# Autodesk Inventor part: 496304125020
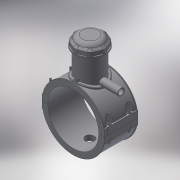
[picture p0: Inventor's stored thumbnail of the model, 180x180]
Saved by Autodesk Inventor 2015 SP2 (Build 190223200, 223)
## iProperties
Created: 2017-07
Part Number: 496304125020
Material: Generic
Description: PLASSON TAPPING SADDLE 125x20
Document SubType Name: Modeling
Designer: KIM
Mass: 805.718 g
Surface Area: 1766.05 cm^2
Volume: 805.718 cm^3
Density: 1 g/cm^3
Appearance: Default
Author: KIM
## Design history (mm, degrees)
derived "496304.ipt"
feature "Solid1::496304.ipt"
feature "Solid2::496304.ipt"
feature "Solid4::496304.ipt"
feature "Solid5::496304.ipt"
tag "TaggingFeature1"
body "Solid1"
body "Solid2"
other parameters: "d0" = 125, "d2" = 162, "d3" = 31.25, "d4" = 118, "d5" = 0, "d6" = 0.1, "d8" = 0, "d19" = 6, "d20" = 6, "d21" = 70.8, "d23" = 0, "d24" = 35.4, "d26" = 0, "d29" = 3, "d30" = 41.66667, "d31" = 6, "d32" = 0, "d33" = 0, "d34" = 0.6, "d40" = 78, "d41" = 62.5, "d43" = 0, "d45" = 0, "d47" = 145.8, "d70" = 15, "d72" = 0, "d73" = 6, "d75" = 5, "d76" = 0, "d77" = 6.25, "d78" = 92.5, "d79" = 15, "d80" = 47.2, "d82" = 5 deg, "d84" = 4, "d85" = 14, "d86" = 0, "d87" = 3, "d88" = 0, "d89" = 1, "d90" = 1, "d91" = 94.4, "d92" = 0, "d93" = 0.5, "d94" = 65.78947, "d96" = 153, "d97" = 2.36, "d98" = 0, "d102" = 1.25, "d120" = 140 deg, "d121" = 24.228, "d122" = 20 deg, "d126" = 0, "d143" = 128.75, "d145" = 19.23077, "d149" = 1.875, "d150" = 21.15385, "d153" = 118, "d154" = 0, "d156" = 75, "d157" = 160 deg, "d159" = 5, "d161" = 1.875, "d162" = 70.8, "d163" = 0, "d164" = 62.5, "d167" = 12.5, "d168" = 73.17073, "d170" = 3.375, "d172" = 0, "d173" = 1, "d175" = 62.5, "d176" = 20 deg, "d177" = 8.75, "d178" = 25, "d180" = 0, "d184" = 7, "d185" = 38.35, "d186" = 38.35, "d187" = 75, "d188" = 7.5, "d189" = 8.75, "d190" = 0, "d191" = 112.5, "d193" = 6.3, "d194" = 4.13, "d195" = 90 deg, "d197" = 0, "d199" = 0, "d200" = 12.5, "d202" = 0, "d203" = 114, "d204" = 59.375, "d205" = 43.75, "d206" = 53.125, "d207" = 85.5, "d208" = 88.92, "d209" = 106.02, "d210" = 53.75, "d211" = 62.5, "d213" = 5.4, "d216" = 0, "d217" = 12.5, "d218" = 12.5, "d219" = 2.5, "d222" = 125, "d224" = 0, "d230" = 5, "d233" = 6, "d236" = 81, "d237" = 35.4, "d238" = 6.02433, "d240" = 35.4, "d241" = 35.4, "d242" = 35.4, "d243" = 6, "d244" = 35.4, "d245" = 35.4, "d246" = 35.4, "d247" = 6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
